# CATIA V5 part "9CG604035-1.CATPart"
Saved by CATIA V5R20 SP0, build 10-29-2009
Part number: 9CG604035-1
Revision: ANY
Definition: UNKNOWN
Nomenclature: 9CG604035-1
Source: Unknown
Bounding box of the stored display mesh (mm): x -25 to 35, y -18 to 23, z -20 to 20
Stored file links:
  C:\Users\Utente\Desktop\IO LAVORO\3D X SITO CF\CUMSA\3D files CG\CG 604035\9CG604035-1.CATPart
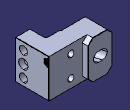
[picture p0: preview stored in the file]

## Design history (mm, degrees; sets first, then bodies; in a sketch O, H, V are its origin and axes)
Body1 "Envolver1" (main body)
  Solid1: solid without history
